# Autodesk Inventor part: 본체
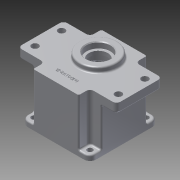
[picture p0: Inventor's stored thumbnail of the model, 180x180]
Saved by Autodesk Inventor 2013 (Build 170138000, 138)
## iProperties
Created: 2015-07
Part Number: 본체
Material: 알루미늄 6061
Document SubType Name: Modeling
Designer: user
Density: 2.71 g/cm^3
Mass: 705.358 g
Surface Area: 672.962 cm^2
Volume: 260.28 cm^3
Author: user
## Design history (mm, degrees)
sketch "스케치1"
  geometry: L1 (-37, 45)-(37, 45); L2 (45, 37)-(45, -37); L3 (37, -45)-(-37, -45); L4 (-45, -37)-(-45, 37); L5 (-45, 45)-(45, -45); L6 (45, 45)-(-45, -45); A1 r 8 centre (-37, 37) between (-37, 45) and (-45, 37); A2 r 8 centre (37, 37) between (45, 37) and (37, 45); A3 r 8 centre (37, -37) between (37, -45) and (45, -37); A4 r 8 centre (-37, -37) between (-45, -37) and (-37, -45); 1 further point
  constraints: 12 end point, 8 point on circle, 8 point on line, 8 tangent, 4 centre point, 3 equal radius, 2 midpoint, 2 parallel, 1 horizontal, 1 perpendicular
  dimensions: "d0" = 90 distance of L5.end L6.end; "d1" = 90 distance of L6.start L5.end; "d2" = 8 radius of A1
extrude "돌출1" new body sketch "스케치1" distance "d3" = 70; taper "d4" = 0 deg
sketch "스케치2"
  geometry: L1 (30, 35)-(30, 61.465); L2 (35, 30)-(85.912, 30); L3 (30, 61.465)-(85.912, 30); L4 (37, 45)-(-37, 45) reference; L5 (0, 0)-(0, 77.772); L6 (-30, 35)-(-30, 61.465); L7 (-35, 30)-(-85.912, 30); L8 (-30, 61.465)-(-85.912, 30); L9 (0, 0)-(60.456, 0); L10 (30, -35)-(30, -61.465); L11 (30, -61.465)-(85.912, -30); L12 (35, -30)-(85.912, -30); L13 (-30, -61.465)-(-85.912, -30); L14 (-30, -35)-(-30, -61.465); L15 (-35, -30)-(-85.912, -30); A1 r 5 centre (35, 35) between (30, 35) and (35, 30); A2 r 5 centre (-35, 35) between (-35, 30) and (-30, 35); A3 r 5 centre (35, -35) between (35, -30) and (30, -35); A4 r 5 centre (-35, -35) between (-30, -35) and (-35, -30)
  constraints: 28 end point, 15 symmetric about line, 8 point on circle, 4 centre point, 2 perpendicular, 2 tangent, 1 parallel, 3 other
  dimensions: "d7" = 5 radius of A1
extrude "돌출4" cut sketch "스케치2" distance "d15" = 63; taper "d16" = 0 deg
sketch "스케치6"
  geometry: L1 (-60, 30)-(60, 30); L2 (65, 25)-(65, -25); L3 (60, -30)-(-60, -30); L4 (-65, -25)-(-65, 25); L5 (-65, 30)-(65, -30); L6 (65, 30)-(-65, -30); L7 (-55, 17.5)-(55, -17.5); L8 (55, 17.5)-(-55, -17.5); C1 r 4.5 at (55, 17.5); C2 r 4.5 at (-55, 17.5); C3 r 4.5 at (-55, -17.5); C4 r 4.5 at (55, -17.5); A1 r 5 centre (60, 25) between (65, 25) and (60, 30); A2 r 5 centre (-60, 25) between (-60, 30) and (-65, 25); A3 r 5 centre (-60, -25) between (-65, -25) and (-60, -30); A4 r 5 centre (60, -25) between (60, -30) and (65, -25); 1 further point
  constraints: 16 end point, 8 centre point, 8 point on circle, 8 point on line, 8 tangent, 4 coincident, 4 midpoint, 3 equal radius, 2 parallel, 1 horizontal, 1 perpendicular
  dimensions: "d17" = 130 distance of L5.end L6.end; "d18" = 60 distance of L6.start L5.end; "d19" = 5 radius of A1; "d20" = 110 distance of L7.end L8.end; "d21" = 35 distance of L8.start L7.end; "d22" = 9 diameter of C1; "d23" = 9 diameter of C2; "d24" = 9 diameter of C3; "d25" = 9 diameter of C4
extrude "돌출5" join sketch "스케치6" distance "d26" = 12; taper "d27" = 0 deg
sketch "스케치7"
  geometry: C1 r 3.5 at (-37, 37); C2 r 3.5 at (37, 37); C3 r 3.5 at (-37, -37); C4 r 3.5 at (37, -37); A1 r 8 centre (37, 37) between (45, 37) and (37, 45) reference; A2 r 8 centre (-37, 37) between (-37, 45) and (-45, 37) reference; A3 r 8 centre (-37, -37) between (-45, -37) and (-37, -45) reference; A4 r 8 centre (37, -37) between (37, -45) and (45, -37) reference; 1 further point
  constraints: 4 centre point, 4 coincident
  dimensions: "d28" = 7 diameter of C1; "d29" = 7 diameter of C2; "d30" = 7 diameter of C3; "d31" = 7 diameter of C4
extrude "돌출6" cut sketch "스케치7" stored distance "d32" = 12; taper "d33" = 0 deg
sketch "스케치8"
  geometry: C1 r 40 at (0, 0); 1 further point
  constraints: 1 centre point, 1 coincident
  dimensions: "d34" = 80 diameter of C1
extrude "돌출7" cut sketch "스케치8" distance "d35" = 9; taper "d36" = 0 deg
sketch "스케치9"
  geometry: C1 r 40 at (0, 0) reference; C2 r 39 at (0, 0)
  constraints: 1 centre point, 1 coincident
  dimensions: "d37" = 78 diameter of C2
extrude "돌출8" cut sketch "스케치9" distance "d38" = 52; taper "d39" = 0 deg
sketch "스케치10"
  geometry: L1 (0, 0)-(0, 11); L2 (0, 0)-(0, -20); C1 r 39 at (0, 0) reference; A1 r 20.5 centre (0, 11) between (11.115, -6.225) and (-11.115, -6.225); A2 r 14 centre (0, -20) between (-10.493, -10.732) and (10.493, -10.732); A3 r 3 centre (-12.742, -8.746) between (-10.493, -10.732) and (-11.115, -6.225); A4 r 3 centre (12.742, -8.746) between (11.115, -6.225) and (10.493, -10.732)
  constraints: 8 point on circle, 4 centre point, 4 end point, 4 tangent, 2 coincident, 1 collinear, 1 equal radius, 1 vertical
  dimensions: "d40" = 11 distance of L1.start L1.end; "d41" = 41 diameter of A1; "d45" = 20 distance of L1.start L2.end; "d46" = 28 diameter of A2; "d47" = 3 radius of A3
extrude "돌출9" join sketch "스케치10" distance "d42" = 7; taper "d43" = 0 deg
sketch "스케치12"
  geometry: C1 r 17.5 at (0, 11); A1 r 20.5 centre (0, 11) between (11.115, -6.225) and (-11.115, -6.225) reference; 1 further point
  constraints: 1 centre point, 1 coincident
  dimensions: "d48" = 35 diameter of C1
sketch "스케치13"
  geometry: L1 (60, 30)-(35, 30) reference; L2 (0, 0)-(0, 11); C1 r 25 at (0, 11)
  constraints: 2 end point, 1 centre point, 1 coincident, 1 perpendicular
  dimensions: "d50" = 11 distance of L2.start L2.end; "d51" = 50 diameter of C1
extrude "돌출10" join sketch "스케치13" distance "d52" = 7; taper "d53" = 0 deg
extrude "돌출11" cut sketch "스케치12" distance "d54" = 10; taper "d55" = 0 deg
sketch "스케치14"
  geometry: C1 r 17.5 at (0, 0) reference; C2 r 12.5 at (0, 0); 1 further point
  constraints: 1 centre point, 1 coincident
  dimensions: "d56" = 25 diameter of C2
extrude "돌출12" cut sketch "스케치14" distance "d57" = 5; taper "d58" = 0 deg
sketch "스케치15"
  geometry: C1 r 16 at (0, 0); 1 further point
  constraints: 1 centre point
  dimensions: "d59" = 32 diameter of C1
extrude "돌출13" cut sketch "스케치15" distance "d60" = 8; taper "d61" = 0 deg
sketch "스케치16"
  geometry: C1 r 11 at (0, -20); A1 r 14 centre (0, -20) between (-10.493, -10.732) and (10.493, -10.732) reference; 1 further point
  constraints: 1 centre point, 1 coincident
  dimensions: "d62" = 22 diameter of C1
extrude "돌출14" cut sketch "스케치16" distance "d63" = 7; taper "d64" = 0 deg
sketch "스케치17"
  geometry: C1 r 11 at (0, 0) reference; C2 r 9.5 at (0, 0); 1 further point
  constraints: 1 centre point, 1 coincident
  dimensions: "d65" = 19 diameter of C2
extrude "돌출15" cut sketch "스케치17" distance "d66" = 1; taper "d67" = 0 deg
fillet "모깎기1" dims "d68" = 2
fillet "모깎기2" dims "d69" = 0.3
chamfer "모따기1" distance "d70" = 1; stored, may be unused: second distance "d71" = 2, angle "d72" = 45 deg
sketch "스케치18"
  geometry: L1 (0, 0)-(31.909, 0); L2 (0, 0)-(24.749, 24.749); C1 r 40 at (0, 0) reference; A1 r 39 centre (0, 0) between (21.134, 32.777) and (32.777, 21.134) reference; A2 r 4 centre (24.749, 24.749) between (21.809, 27.462) and (27.462, 21.809); A3 r 3.5 centre (19.238, 29.836) between (21.809, 27.462) and (21.134, 32.777); A4 r 3.5 centre (29.836, 19.238) between (32.777, 21.134) and (27.462, 21.809); A5 r 39 centre (0, 0) between (32.777, 21.134) and (21.134, 32.777)
  constraints: 10 point on circle, 4 centre point, 4 end point, 2 coincident, 2 tangent, 1 concentric, 1 horizontal, 1 symmetric about line, 1 other
  dimensions: "d74" = 35 distance of L1.start L2.end; "d75" = 45 deg angle of L1 L2; "d76" = 8 diameter of A2; "d77" = 7 diameter of A3
extrude "돌출16" join sketch "스케치18" stored distance "d78" = 1; taper "d79" = 0 deg
sketch "스케치19"
  geometry: L1 (-30, -45)-(30, -45) reference; L2 (60, 30)-(35, 30) reference; L3 (0, -45)-(0, -30); 2 further points
  constraints: 2 end point, 1 coincident, 1 midpoint, 1 perpendicular, 1 other
  dimensions: "d83" = 15 distance of L3.start L3.end
feature "엠보싱1" sketch "스케치19" dims "d0" = 90, "d1" = 90, "d2" = 8, "d84" = 0.5, "d85" = 0
fillet "모깎기3" dims "d86" = 2
fillet "모깎기4" dims "d87" = 2
fillet "모깎기5" dims "d88" = 2
fillet "모깎기6" dims "d89" = 2
fillet "모깎기7" dims "d90" = 2
fillet "모깎기8" dims "d91" = 2
sketch "스케치20"
  geometry: A1 r 4 centre (24.749, 24.749) between (21.809, 27.462) and (27.462, 21.809) reference
hole "구멍1" sketch "스케치20" at (24.749, 24.749) diameter "d92" = 3.459; stored, may be unused: countersink angle "d96" = 90 deg, drill point angle "d98" = 118 deg; dims "d93" = 12, "d94" = 4, "d95" = 2, "d97" = 15
node "솔리드1"
pattern_circular "원형 패턴2" dims angle "d81" = 360 deg
pattern_circular "원형 패턴3" dims angle "d100" = 360 deg
